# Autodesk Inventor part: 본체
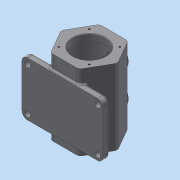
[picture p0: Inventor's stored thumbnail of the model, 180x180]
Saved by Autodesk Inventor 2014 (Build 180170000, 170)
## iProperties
Created: 2021-06
Part Number: 본체
Material: 일반
Document SubType Name: Modeling
Designer: net
Density: 1 g/cm^3
Appearance: 기본값
Author: net
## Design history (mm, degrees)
sketch "스케치1" dims "d0" = 105
  geometry: L1 (-52.5, 0)-(-26.25, 45.466); L2 (-26.25, 45.466)-(26.25, 45.466); L3 (26.25, 45.466)-(52.5, 0); L4 (52.5, 0)-(26.25, -45.466); L5 (26.25, -45.466)-(-26.25, -45.466); L6 (-26.25, -45.466)-(-52.5, 0); 3 further points
  constraints: 12 end point, 2 coincident, 1 horizontal alignment, 15 other
  dimensions: "d1" = 45.46633 vertical distance of L2.end L3.end
extrude "돌출1" new body sketch "스케치1" distance "d2" = 140; taper "d3" = 0 deg
node "작업 평면1"
sketch "스케치2"
  geometry: L1 (-52.5, 0)-(-26.25, 45.466) reference; L2 (-26.25, 45.466)-(26.25, 45.466) reference; L3 (26.25, 45.466)-(52.5, 0) reference; L4 (52.5, 0)-(26.25, -45.466) reference; L5 (26.25, -45.466)-(-26.25, -45.466) reference; L6 (-26.25, -45.466)-(-52.5, 0) reference; L7 (-75, -50)-(75, -50); L8 (75, -50)-(75, -38); L9 (75, -38)-(-75, -38); L10 (-75, -38)-(-75, -50); 2 further points
  constraints: 8 end point, 2 parallel, 1 horizontal, 1 midpoint, 1 perpendicular, 1 vertical alignment
  dimensions: "d5" = 12 distance of L7.end L8.end; "d6" = 50 distance from line of L7 point (0, 0); "d7" = 150 distance of L7.start L7.end
extrude "돌출2" join sketch "스케치2" distance "d8" = 100; taper "d9" = 0 deg
node "작업 평면2"
sketch "스케치3"
  geometry: L1 (0, 12)-(0, 4.534) reference; L2 (0, 4.534)-(-25, 4.534) reference; L3 (-25, 50)-(-25, 4.534) reference; L4 (115, 50)-(-25, 50) reference; L5 (115, 4.534)-(115, 50) reference; L6 (115, 4.534)-(100, 4.534) reference; L7 (100, 4.534)-(100, 12) reference; L8 (100, 12)-(0, 12) reference; L9 (115, 50)-(115, 95.466) reference; L10 (115, 50)-(-25, 50) reference; L11 (-25, 95.466)-(-25, 50) reference; L12 (115, 95.466)-(-25, 95.466) reference; L13 (-25, 50)-(115, 50); L14 (-25, 50)-(-25, 80); L15 (-25, 80)-(-13, 80); L16 (-13, 80)-(-13, 87.5); L17 (-13, 87.5)-(103, 87.5); L18 (103, 87.5)-(103, 80); L19 (103, 80)-(115, 80); L20 (115, 50)-(115, 80); 1 further point
  constraints: 16 end point, 3 perpendicular, 3 point on line, 1 collinear, 1 parallel
  dimensions: "d10" = 12 distance of L14.end L15.end; "d11" = 12 distance of L18.end L19.end; "d12" = 60 diameter of L19 L4; "d13" = 60 diameter of L15 L4; "d14" = 75 diameter of L17 L4
revolve "회전1" sketch "스케치3" stored, may be unused: angle "d15" = 90 deg
chamfer "모따기1" distance "d16" = 1; stored, may be unused: second distance "d17" = 2, angle "d18" = 45 deg
fillet "모깎기1" dims "d19" = 5
fillet "모깎기2" dims "d20" = 5
sketch "스케치4"
  geometry: L1 (52.5, -140)-(0, -140) reference; 4 further points
  constraints: 2 vertical alignment, 1 midpoint
  dimensions: "d21" = 40 distance from line of L1 point (26.25, -100); "d22" = 60 distance of point (26.25, -40) point (26.25, -100)
hole "구멍1" sketch "스케치4" at (26.25, -100), (26.25, -40) diameter "d23" = 25; stored, may be unused: countersink angle "d27" = 90 deg, drill point angle "d29" = 0 deg; dims "d24" = 6, "d25" = 4, "d26" = 2, "d28" = 10
node "작업 평면3"
sketch "스케치5"
  geometry: L1 (26.25, 0)-(-26.25, 0) reference; L2 (26.25, 0)-(26.25, 140) reference; L3 (-26.25, 140)-(26.25, 140) reference; L4 (-26.25, 0)-(-26.25, 140) reference; C1 r 12.5 at (0, 100) reference; C2 r 12.5 at (0, 40) reference; C3 r 20 at (0, 100); C4 r 20 at (0, 40); 1 further point
  constraints: 2 centre point, 2 coincident, 1 equal radius
  dimensions: "d31" = 40 diameter of C3
extrude "돌출3" join sketch "스케치5" stored distance "d32" = 100; taper "d33" = 0 deg
sketch "스케치6"
  geometry: C1 r 12.5 at (0, 0) reference; C2 r 12.5 at (0, 60) reference; C3 r 20 at (0, 60) reference; 1 further point
hole "구멍2" sketch "스케치6" at (0, 0), (0, 60) diameter "d34" = 30; stored, may be unused: countersink angle "d38" = 90 deg, drill point angle "d40" = 0 deg; dims "d35" = 6, "d36" = 4, "d37" = 2, "d39" = 8
fillet "모깎기3" dims "d41" = 10
sketch "스케치7"
  geometry: L1 (105.561, 10)-(105.561, 90) reference; L2 (61.121, 100)-(95.561, 100) reference; L3 (61.121, 0)-(61.121, 100) reference; L4 (95.561, 0)-(61.121, 0) reference; A1 r 10 centre (-34.439, 10) between (-44.439, 10) and (-34.439, 0) reference; A2 r 10 centre (-34.439, 90) between (-34.439, 100) and (-44.439, 90) reference; A3 r 10 centre (95.561, 10) between (95.561, 0) and (105.561, 10) reference; A4 r 10 centre (95.561, 90) between (105.561, 90) and (95.561, 100) reference; 1 further point
hole "구멍3" sketch "스케치7" at (-34.439, 10), (-34.439, 90), (95.561, 90), (95.561, 10) diameter "d42" = 11; stored, may be unused: countersink angle "d46" = 90 deg, drill point angle "d48" = 0 deg; dims "d43" = 6, "d44" = 4, "d45" = 2, "d47" = 8
sketch "스케치8"
  geometry: L1 (0, 0)-(-34.439, 0) reference; L2 (-44.439, 10)-(-44.439, 90) reference; 2 further points
  constraints: 1 other
  dimensions: "d49" = 50 distance from line of L1 point (-30.439, 50); "d50" = 14 distance from line of point (-30.439, 50) L2
extrude "돌출4" join sketch "스케치8" distance "d51" = 0.5; taper "d52" = 0 deg
fillet "모깎기4" dims "d53" = 3
fillet "모깎기5" dims "d54" = 8
fillet "모깎기6" dims "d55" = 3
fillet "모깎기7" dims "d56" = 3
node "작업 평면4"
sketch "스케치10"
  geometry: L1 (21.631, 45.466)-(-21.631, 45.466) reference; L2 (0, 0)-(0, 40); L3 (0, 0)-(-28.284, 28.284); C1 r 31 at (0, 0) reference; A1 r 40 centre (0, 0) between (0, 40) and (-28.284, 28.284); 1 further point
  constraints: 4 end point, 2 coincident, 2 point on circle, 1 centre point, 1 perpendicular
  dimensions: "d69" = 80 diameter of A1; "d70" = 45 deg angle of L3 L2
hole "구멍5" sketch "스케치10" at (-28.284, 28.284) diameter "d71" = 3.242; stored, may be unused: countersink angle "d75" = 90 deg, drill point angle "d77" = 118 deg; dims "d72" = 8, "d73" = 4, "d74" = 2, "d76" = 10
sketch "스케치11" dims "d81" = 80
  geometry: C1 r 31 at (0, 0) reference; 2 further points
  constraints: 2 vertical alignment, 1 coincident, 2 other
hole "구멍6" sketch "스케치11" at (0, 40) diameter "d82" = 3.242; stored, may be unused: countersink angle "d86" = 90 deg, drill point angle "d88" = 118 deg; dims "d83" = 8, "d84" = 4, "d85" = 2, "d87" = 10
node "솔리드1"
pattern_circular "원형 패턴2" dims angle "d79" = 360 deg
pattern_circular "원형 패턴3" dims angle "d90" = 360 deg
node "투영된 루프1"
node "투영된 루프2"
node "투영된 루프3"
node "투영된 루프4"
node "투영된 루프5"
node "투영된 루프6"
other parameters: "d4" = -25, "d30" = 52.5
